Omron CX-Programmer project NuevoProyecto (CX-Programmer 9.50)

# PLC NewPLC1: CP1L-E EM

## Program P17_1_2 (cyclic task 0)
Local symbols
EV1 100.01 BOOL
EV2 100.02 BOOL
EV3 100.03 BOOL
Etapa_0 10.00 BOOL
Etapa_1 10.01 BOOL
Etapa_10 10.10 BOOL
Etapa_2 10.02 BOOL
Etapa_3 10.03 BOOL
Etapa_4 10.04 BOOL
Etapa_5 10.05 BOOL
Etapa_6 10.06 BOOL
Etapa_7 10.07 BOOL
Etapa_8 10.08 BOOL
Etapa_9 10.09 BOOL
F1 0.02 BOOL
FSF1 15.00 BOOL  ; Flanco Subida F1
MC 100.00 BOOL
S_1 0.01 BOOL
X 15.01 BOOL  ; Auxiliar X
Xm 15.02 BOOL  ; Auxiliar X memorizada
Y 15.03 BOOL  ; Auxiliar Y
Ym 15.04 BOOL  ; Auxiliar Y memorizada
m 0.00 BOOL

### Section Sección1_Programa_principal
; Programa principal (Etapas 0 ... 23)

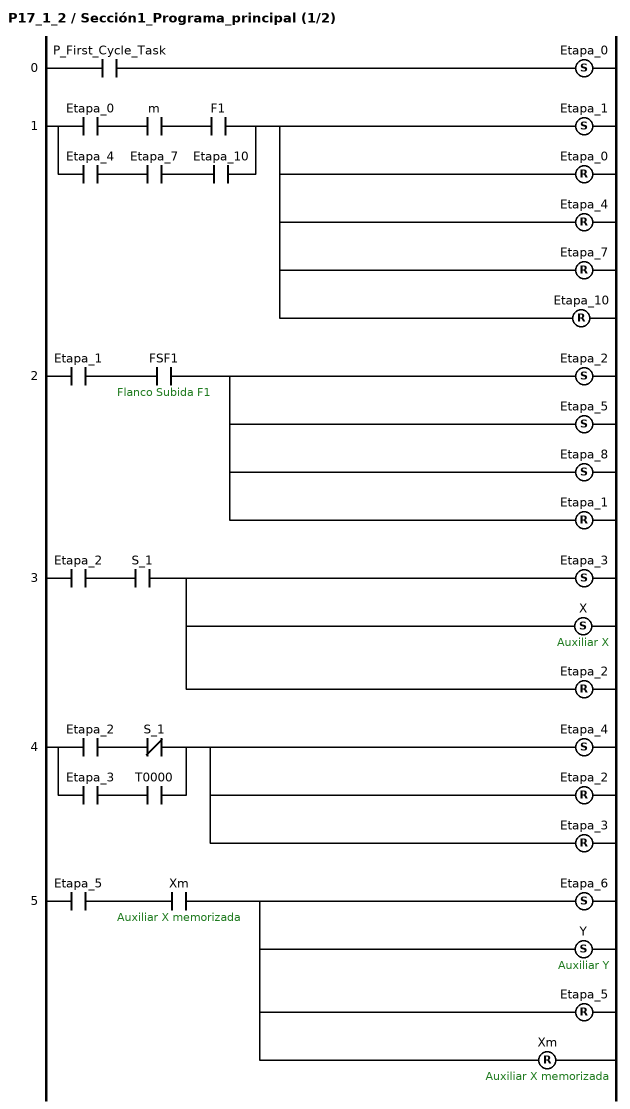
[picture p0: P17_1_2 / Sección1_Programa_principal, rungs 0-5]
; rung 0
LD P_First_Cycle_Task
SET Etapa_0
; rung 1
LD Etapa_0
AND m
AND F1
LD Etapa_4
AND Etapa_7
AND Etapa_10
ORLD
SET Etapa_1
RSET Etapa_0
RSET Etapa_4
RSET Etapa_7
RSET Etapa_10
; rung 2
LD Etapa_1
AND FSF1  ; Flanco Subida F1
SET Etapa_2
SET Etapa_5
SET Etapa_8
RSET Etapa_1
; rung 3
LD Etapa_2
AND S_1
SET Etapa_3
SET X  ; Auxiliar X
RSET Etapa_2
; rung 4
LD Etapa_2
ANDNOT S_1
LD Etapa_3
AND T0000
ORLD
SET Etapa_4
RSET Etapa_2
RSET Etapa_3
; rung 5
LD Etapa_5
AND Xm  ; Auxiliar X memorizada
SET Etapa_6
SET Y  ; Auxiliar Y
RSET Etapa_5
RSET Xm  ; Auxiliar X memorizada

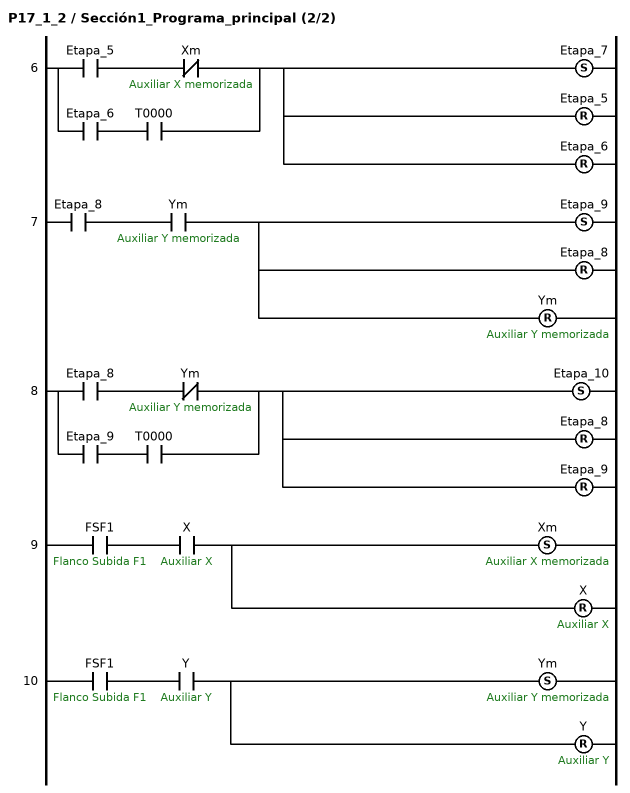
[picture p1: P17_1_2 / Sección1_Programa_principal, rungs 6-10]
; rung 6
LD Etapa_5
ANDNOT Xm  ; Auxiliar X memorizada
LD Etapa_6
AND T0000
ORLD
SET Etapa_7
RSET Etapa_5
RSET Etapa_6
; rung 7
LD Etapa_8
AND Ym  ; Auxiliar Y memorizada
SET Etapa_9
RSET Etapa_8
RSET Ym  ; Auxiliar Y memorizada
; rung 8
LD Etapa_8
ANDNOT Ym  ; Auxiliar Y memorizada
LD Etapa_9
AND T0000
ORLD
SET Etapa_10
RSET Etapa_8
RSET Etapa_9
; rung 9
LD FSF1  ; Flanco Subida F1
AND X  ; Auxiliar X
SET Xm  ; Auxiliar X memorizada
RSET X  ; Auxiliar X
; rung 10
LD FSF1  ; Flanco Subida F1
AND Y  ; Auxiliar Y
SET Ym  ; Auxiliar Y memorizada
RSET Y  ; Auxiliar Y

### Section Sección2_Temporizador

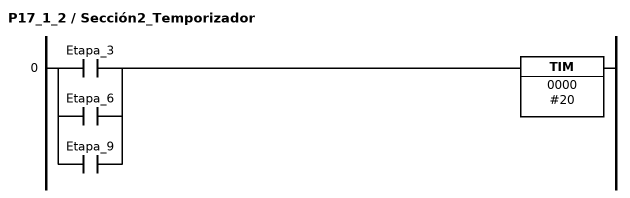
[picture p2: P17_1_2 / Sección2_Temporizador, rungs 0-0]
; rung 0
LD Etapa_3
OR Etapa_6
OR Etapa_9
TIM 0000 #20

### Section Sección3_FSF1

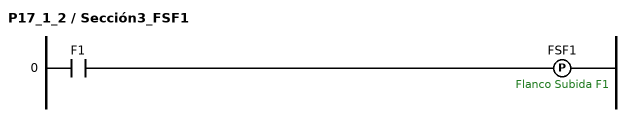
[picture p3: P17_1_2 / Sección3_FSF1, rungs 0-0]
; rung 0
LD F1
DIFU(013) FSF1  ; Flanco Subida F1

### Section Sección4_Salidas

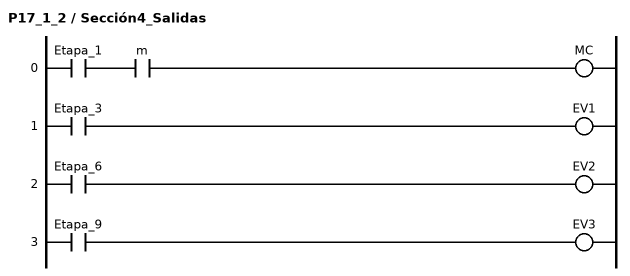
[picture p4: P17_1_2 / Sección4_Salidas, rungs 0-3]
; rung 0
LD Etapa_1
AND m
OUT MC
; rung 1
LD Etapa_3
OUT EV1
; rung 2
LD Etapa_6
OUT EV2
; rung 3
LD Etapa_9
OUT EV3

### Section Sección5_END
; rung 0: Fin de programa
END(001)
